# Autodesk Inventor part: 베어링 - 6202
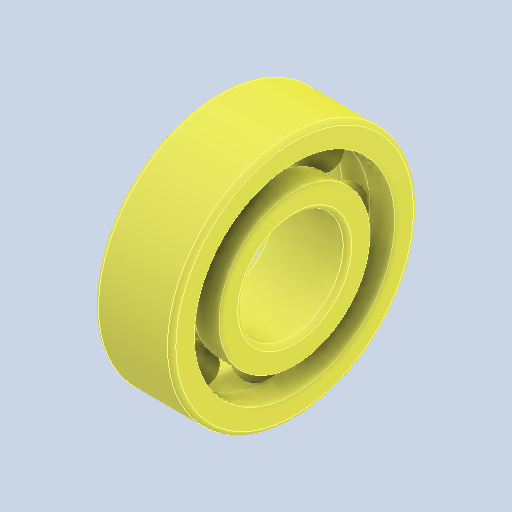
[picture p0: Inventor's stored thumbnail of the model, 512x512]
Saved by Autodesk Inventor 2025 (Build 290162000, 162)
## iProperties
Created: 2024-07
Part Number: 베어링 - 6202
Material: 강, 연강
Description: 깊은 그루브 볼 베어링
Document SubType Name: Modeling
Designer: anfro
Density: 7.86 g/cm^3
Appearance: 기본값
Author: jhkim
Sending System: Autodesk Inventor 2025
Preprocessor: ST-DEVELOPER v20
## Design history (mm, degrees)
feature "Solid1"
feature "Solid1:1"
feature "Solid1:2"
feature "Solid1:3"
feature "Solid1:4"
feature "Solid1:5"
feature "Solid1:6"
feature "Solid1:7"
feature "Solid1:8"
feature "Solid1:9"
node "솔리드1"
node "솔리드2"
node "솔리드3"
node "솔리드4"
node "솔리드5"
node "솔리드6"
node "솔리드7"
node "솔리드8"
node "솔리드9"
node "솔리드10"
